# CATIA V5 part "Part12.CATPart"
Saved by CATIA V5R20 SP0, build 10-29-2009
Part number: 3IMAN5X2
Revision: ANY
Definition: UNKNOWN
Nomenclature: 3IMAN5X2
Source: Unknown
Bounding box of the stored display mesh (mm): x -2.5 to 2.5, y 0 to 2, z -2.5 to 2.5
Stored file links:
  C:\Users\Utente\Desktop\IO LAVORO\3D X SITO CF\CUMSA\3D files CG\CG 604035\Part12.CATPart
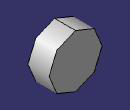
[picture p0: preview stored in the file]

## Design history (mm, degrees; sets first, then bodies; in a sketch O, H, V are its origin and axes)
Body1 "Saliente-Extruir1" (main body)
  Solid1: solid without history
